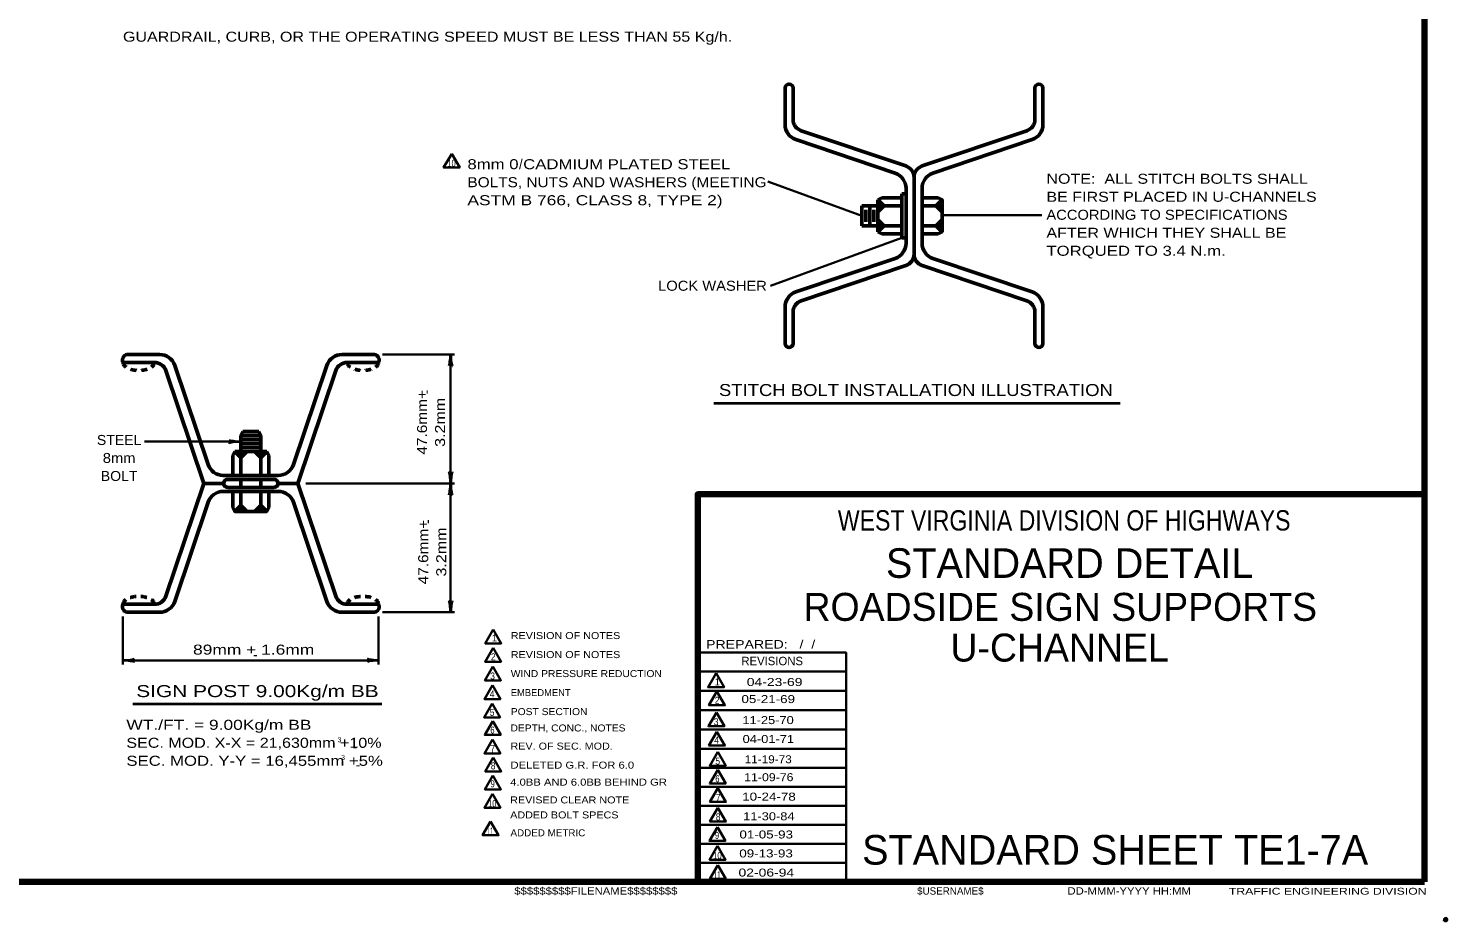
# Model space of a CAD drawing. Extents: x -39 to 816, y -2 to 542.
# Drawn here: x 390.9 to 816.3, y -1.7 to 265.9 of the extents above; entities that cross this region are included whole.
import ezdxf
from ezdxf.enums import TextEntityAlignment as Align

# ---------------------------------------------------------------- set-up
doc = ezdxf.new("R2010")
doc.units = 0
doc.header["$LTSCALE"] = 1.2
doc.header["$PDMODE"] = 32
doc.header["$PDSIZE"] = 0.6
doc.linetypes.add('SHORT_DASHED', pattern=[2.7, 1.5, -1.2])
doc.layers.add('1', color=7, linetype='Continuous', lineweight=53)
doc.layers.add('61', color=7, linetype='Continuous', lineweight=35)

msp = doc.modelspace()

# ---------------------------------------------------------------- linework, layer by layer
at = {"layer": '1', "lineweight": 158}
for q in [(809.673, 536.027), (809.673, 126.227), (18.073, 9.927)]:
    msp.add_line((809.673, 9.927), q, dxfattribs=at)
at = {"layer": '1', "lineweight": 13}
msp.add_line((809.673, 9.927), (809.673, 536.027), dxfattribs=at)
at = {"layer": '1'}
for p, q in [((617.877, 237.1), (617.877, 248.053)), ((620.277, 238.639), (620.277, 248.053)), ((692.81, 238.639), (692.81, 248.053)), ((695.21, 237.1), (695.21, 248.053)), ((654.093, 224.65), (622.727, 235.227)), ((658.993, 224.65), (690.36, 235.227)), ((650.877, 222.525), (621.143, 232.552)), ((662.209, 222.525), (691.943, 232.552)), ((656.543, 198.209), (656.543, 221.239)), ((654.143, 201.471), (654.143, 217.977)), ((658.943, 201.471), (658.943, 217.977)), ((640.943, 206.724), (640.943, 212.724)), ((643.343, 206.724), (643.343, 212.724)), ((645.743, 214.524), (646.943, 215.124)), ((645.743, 204.924), (645.743, 214.524)), ((646.943, 215.124), (652.943, 215.124)), ((654.143, 216.324), (652.943, 216.324)), ((652.943, 216.324), (652.943, 203.124)), ((658.943, 215.124), (663.743, 215.124)), ((658.943, 212.724), (664.943, 212.724)), ((664.943, 214.524), (663.743, 215.124)), ((664.943, 204.924), (664.943, 214.524)), ((642.143, 207.924), (642.143, 211.524)), ((644.543, 207.924), (644.543, 211.524)), ((645.743, 204.924), (646.943, 204.324)), ((646.943, 204.324), (652.943, 204.324)), ((658.943, 206.724), (664.943, 206.724)), ((658.943, 204.324), (663.743, 204.324)), ((664.943, 204.924), (663.743, 204.324)), ((654.143, 203.124), (652.943, 203.124)), ((650.877, 196.923), (621.143, 186.896)), ((662.209, 196.923), (691.943, 186.896)), ((654.094, 194.798), (622.727, 184.221)), ((658.993, 194.798), (690.36, 184.221)), ((617.877, 182.348), (617.877, 171.395)), ((620.277, 180.81), (620.277, 171.395)), ((692.81, 180.81), (692.81, 171.395)), ((695.21, 182.348), (695.21, 171.395)), ((430.279, 168.123), (420.526, 168.123)), ((485.031, 168.123), (494.784, 168.123)), ((428.741, 165.723), (419.326, 165.723)), ((443.555, 129.456), (432.152, 163.273)), ((444.854, 135.123), (434.827, 164.856)), ((470.457, 135.123), (480.483, 164.856)), ((471.755, 129.456), (483.158, 163.273)), ((486.57, 165.723), (495.984, 165.723)), ((455.255, 145.056), (454.655, 143.856)), ((455.255, 145.056), (460.055, 145.056)), ((460.055, 145.056), (460.655, 143.856)), ((454.655, 143.856), (460.655, 143.856)), ((454.655, 142.656), (460.655, 142.656)), ((454.655, 141.456), (460.655, 141.456)), ((452.855, 139.056), (452.255, 137.856)), ((452.255, 137.856), (452.255, 131.856)), ((452.855, 139.056), (462.455, 139.056)), ((454.655, 140.256), (460.388, 140.256)), ((462.455, 139.056), (463.055, 137.856)), ((463.055, 137.856), (463.055, 131.856)), ((449.402, 131.856), (465.908, 131.856)), ((443.555, 129.456), (432.152, 95.64)), ((443.555, 129.456), (449.492, 129.456)), ((450.755, 130.656), (464.555, 130.656)), ((450.755, 128.256), (464.555, 128.256)), ((454.655, 130.656), (454.655, 128.256)), ((460.655, 130.656), (460.655, 128.256)), ((465.818, 129.456), (471.755, 129.456)), ((471.755, 129.456), (483.158, 95.64)), ((444.854, 123.79), (434.827, 94.056)), ((449.402, 127.056), (465.908, 127.056)), ((452.255, 127.056), (452.255, 122.256)), ((454.655, 127.056), (454.655, 121.056)), ((460.655, 127.056), (460.655, 121.056)), ((463.055, 127.056), (463.055, 122.256)), ((470.457, 123.79), (480.483, 94.056)), ((452.855, 121.056), (452.255, 122.256)), ((452.855, 121.056), (462.455, 121.056)), ((462.455, 121.056), (463.055, 122.256)), ((428.741, 93.19), (419.326, 93.19)), ((430.279, 90.79), (420.526, 90.79)), ((485.031, 90.79), (494.784, 90.79)), ((486.57, 93.19), (495.984, 93.19))]:
    msp.add_line(p, q, dxfattribs=at)
at = {"layer": '1', "lineweight": 35}
for p, q in [((640.943, 209.724), (612.752, 219.985)), ((664.9, 209.888), (694.9, 209.888)), ((652.943, 203.124), (613.476, 188.759)), ((497.184, 168.123), (518.784, 168.123)), ((454.573, 141.978), (425.773, 141.978)), ((474.155, 129.456), (518.784, 129.456)), ((419.326, 89.59), (419.326, 75.19)), ((495.984, 89.59), (495.984, 75.19)), ((497.184, 90.79), (518.784, 90.79)), ((419.326, 76.39), (495.984, 76.39)), ((636.173, 73.027), (591.673, 73.027)), ((636.173, 67.227), (591.673, 67.227)), ((636.173, 61.427), (591.673, 61.427)), ((636.173, 55.627), (591.673, 55.627)), ((636.173, 49.827), (591.673, 49.827)), ((636.173, 44.127), (591.673, 44.127)), ((636.173, 38.427), (591.673, 38.427)), ((636.173, 32.727), (591.673, 32.727)), ((636.173, 27.027), (591.673, 27.027)), ((636.173, 21.327), (591.673, 21.327)), ((636.173, 15.627), (591.673, 15.627))]:
    msp.add_line(p, q, dxfattribs=at)
at = {"layer": '1', "lineweight": 40}
for p, q in [((596.486, 153.57), (718.406, 153.57)), ((422.301, 63.357), (496.961, 63.357))]:
    msp.add_line(p, q, dxfattribs=at)
at = {"layer": '1', "lineweight": 35}
for points in [[(517.894, 228.314), (515.494, 224.157), (520.294, 224.157)], [(530.384, 85.638), (527.984, 81.481), (532.784, 81.481)], [(530.312, 80.146), (527.912, 75.99), (532.712, 75.99)], [(530.24, 74.52), (527.84, 70.363), (532.64, 70.363)], [(597.203, 72.496), (594.803, 68.339), (599.603, 68.339)], [(530.136, 68.925), (527.736, 64.768), (532.536, 64.768)], [(597.446, 67.084), (595.046, 62.927), (599.846, 62.927)], [(530.033, 63.434), (527.633, 59.277), (532.433, 59.277)], [(597.295, 60.786), (594.895, 56.629), (599.695, 56.629)], [(530.209, 58.175), (527.809, 54.018), (532.609, 54.018)], [(530.136, 52.621), (527.736, 48.464), (532.536, 48.464)], [(597.446, 54.974), (595.046, 50.817), (599.846, 50.817)], [(530.369, 47.218), (527.969, 43.061), (532.769, 43.061)], [(597.675, 48.931), (595.275, 44.774), (600.075, 44.774)], [(597.675, 43.585), (595.275, 39.428), (600.075, 39.428)], [(530.281, 41.852), (527.881, 37.695), (532.681, 37.695)], [(530.106, 36.349), (527.706, 32.192), (532.506, 32.192)], [(597.76, 38.068), (595.361, 33.911), (600.161, 33.911)], [(597.748, 32.183), (595.348, 28.026), (600.148, 28.026)], [(529.574, 28.074), (527.173, 23.917), (531.974, 23.917)], [(597.574, 26.388), (595.174, 22.231), (599.974, 22.231)], [(597.635, 20.755), (595.235, 16.598), (600.035, 16.598)], [(597.714, 15.009), (595.313, 10.853), (600.114, 10.853)]]:
    msp.add_lwpolyline(points, close=True, dxfattribs=at)
at = {"layer": '1'}
for points in [[(640.943, 212.724), (645.743, 212.724), (652.943, 212.724)], [(640.943, 206.724), (645.743, 206.724), (652.943, 206.724)], [(454.655, 143.856), (454.655, 139.056), (454.655, 131.856)], [(460.655, 143.856), (460.655, 139.056), (460.655, 131.856)]]:
    msp.add_lwpolyline(points, dxfattribs=at)
for points in [[(645.743, 214.524), (645.743, 210.924), (647.543, 212.724)], [(664.943, 210.924), (663.143, 212.724), (664.943, 214.524)], [(645.743, 204.924), (645.743, 208.524), (647.543, 206.724)], [(663.143, 206.724), (664.943, 204.924), (664.943, 208.524)], [(452.855, 139.056), (456.455, 139.056), (454.655, 137.256)], [(462.455, 139.056), (458.855, 139.056), (460.655, 137.256)], [(454.655, 122.856), (452.855, 121.056), (456.455, 121.056)], [(458.855, 121.056), (460.655, 122.856), (462.455, 121.056)]]:
    msp.add_lwpolyline(points, close=True, dxfattribs=at)
at = {"layer": '1', "lineweight": 35}
for points in [[(517.584, 168.123), (517.584, 129.456), (517.584, 90.79)], [(636.173, 9.927), (636.173, 78.727), (591.673, 78.727)]]:
    msp.add_lwpolyline(points, dxfattribs=at)
at = {"layer": '1', "lineweight": 158}
msp.add_lwpolyline([(591.673, 9.927), (591.673, 126.227), (809.673, 126.227)], dxfattribs=at)
at = {"layer": '1'}
for centre, radius, start, end in [((619.077, 247.997), 1.201, 2.66716, 177.33283), ((694.009, 247.997), 1.201, 2.66716, 177.33283), ((623.877, 238.639), 3.6, 180, 251.36548), ((689.21, 238.639), 3.6, 288.63452, 0), ((622.677, 237.1), 4.8, 180, 251.36561), ((690.41, 237.1), 4.8, 288.63439, 360), ((649.343, 217.977), 4.8, 0, 71.36535), ((652.943, 221.239), 3.6, 0, 71.36649), ((660.143, 221.239), 3.6, 108.63574, 180), ((663.743, 217.977), 4.8, 108.63465, 180), ((649.343, 201.471), 4.8, 288.63525, 0), ((663.743, 201.471), 4.8, 180, 251.36475), ((652.943, 198.209), 3.6, 288.63393, 0), ((660.143, 198.209), 3.6, 180, 251.36641), ((622.677, 182.348), 4.8, 108.63408, 180), ((623.877, 180.81), 3.6, 108.63464, 180), ((689.21, 180.81), 3.6, 0, 71.36536), ((690.41, 182.348), 4.8, 0, 71.36592), ((619.077, 171.451), 1.201, 182.66717, 357.33284), ((694.009, 171.451), 1.201, 182.66717, 357.33284), ((420.844, 166.464), 1.689, 100.85533, 206.01456), ((430.279, 163.323), 4.8, 18.63408, 90), ((485.031, 163.323), 4.8, 90, 161.36561), ((494.466, 166.464), 1.689, 333.98544, 79.14467), ((428.741, 162.123), 3.6, 18.63464, 90), ((486.57, 162.123), 3.6, 90, 161.36548), ((449.402, 136.656), 4.8, 198.63525, 270), ((465.908, 136.656), 4.8, 270, 341.36535), ((450.693, 129.456), 1.202, 87.05408, 272.94592), ((464.617, 129.456), 1.202, 267.05408, 92.94592), ((449.402, 122.256), 4.8, 90, 161.36475), ((465.908, 122.256), 4.8, 18.63465, 90), ((428.741, 96.79), 3.6, 270, 341.36536), ((430.279, 95.59), 4.8, 270, 341.36592), ((485.031, 95.59), 4.8, 198.63439, 270), ((486.57, 96.79), 3.6, 198.63452, 270), ((420.844, 92.449), 1.689, 153.98544, 259.14467), ((494.466, 92.449), 1.689, 280.85533, 26.01456)]:
    msp.add_arc(centre, radius, start, end, dxfattribs=at)
at = {"layer": '1', "lineweight": 40}
for centre, major_axis, ratio, start_param, end_param in [((517.33, 166.778), (0.211, 2.108), 0.07063, 3.1407148, 5.41811), ((517.33, 166.778), (0.211, 2.108), 0.07063, 3.1407148, 5.41811), ((517.916, 166.813), (-0.187, 2.143), 0.122415, 0.8963533, 3.1415927), ((517.916, 166.813), (-0.187, 2.143), 0.122415, 0.8963533, 3.1415927), ((453.263, 141.647), (2.143, 0.187), 0.122415, 0.8963533, 3.1415927), ((453.228, 142.232), (2.108, -0.211), 0.07063, 3.1407148, 5.41811), ((517.253, 130.766), (0.187, -2.143), 0.122415, 0.8963533, 3.1415927), ((517.253, 130.766), (0.187, -2.143), 0.122415, 0.8963533, 3.1415927), ((517.838, 130.801), (-0.211, -2.108), 0.07063, 3.1407148, 5.41811), ((517.838, 130.801), (-0.211, -2.108), 0.07063, 3.1407148, 5.41811), ((517.33, 128.112), (0.211, 2.108), 0.07063, 3.1407148, 5.41811), ((517.33, 128.112), (0.211, 2.108), 0.07063, 3.1407148, 5.41811), ((517.916, 128.147), (-0.187, 2.143), 0.122415, 0.8963533, 3.1415927), ((517.916, 128.147), (-0.187, 2.143), 0.122415, 0.8963533, 3.1415927), ((517.253, 92.1), (0.187, -2.143), 0.122415, 0.8963533, 3.1415927), ((517.838, 92.135), (-0.211, -2.108), 0.07063, 3.1407148, 5.41811), ((420.635, 76.722), (-2.143, -0.187), 0.122415, 0.8963533, 3.1415927), ((420.635, 76.722), (-2.143, -0.187), 0.122415, 0.8963533, 3.1415927), ((494.64, 76.644), (2.108, -0.211), 0.07063, 3.1407148, 5.41811), ((420.67, 76.136), (-2.108, 0.211), 0.07063, 3.1407148, 5.41811), ((420.67, 76.136), (-2.108, 0.211), 0.07063, 3.1407148, 5.41811), ((494.675, 76.059), (2.143, 0.187), 0.122415, 0.8963533, 3.1415927)]:
    msp.add_ellipse(centre, major_axis=major_axis, ratio=ratio, start_param=start_param, end_param=end_param, dxfattribs=at)
at = {"layer": '1', "linetype": 'SHORT_DASHED'}
for centre, major_axis, start_param, end_param in [((424.033, 165.723), (4.707, 0), 3.1415927, 6.2831853), ((491.277, 165.723), (-4.707, 0), 6.2831853, 9.424778), ((424.033, 93.19), (4.707, 0), 6.2831853, 9.424778), ((491.277, 93.19), (-4.707, 0), 3.1415927, 6.2831853)]:
    msp.add_ellipse(centre, major_axis=major_axis, ratio=0.50983, start_param=start_param, end_param=end_param, dxfattribs=at)
at = {"layer": '1'}
msp.add_point((815.973, -1.373), dxfattribs=at)
at = {"layer": '61', "lineweight": 53}
for q in [(656.973, 9.927), (656.973, 9.927), (656.973, 9.927), (657.273, 9.927), (657.273, 9.927)]:
    msp.add_line((809.673, 9.927), q, dxfattribs=at)

# ---------------------------------------------------------------- texts
at = {"layer": '1'}
for s, height, width, p in [('GUARDRAIL, CURB, OR THE OPERATING SPEED MUST BE LESS THAN 55 Kg/h.', 3, 1.2, (419.317, 261.927)), ('10', 2.1, 0.8, (516.601, 224.428)), ('8mm 0 CADMIUM PLATED STEEL', 3, 1.25, (522.621, 223.689)), ('BOLTS, NUTS AND WASHERS (MEETING', 3, 1.15, (522.621, 218.289)), ('NOTE:  ALL STITCH BOLTS SHALL', 3, 1.2, (696.249, 219.32)), ('BE FIRST PLACED IN U-CHANNELS', 3, 1.2, (696.249, 213.92)), ('ASTM B 766, CLASS 8, TYPE 2)', 3, 1.3, (522.621, 212.889)), ('ACCORDING TO SPECIFICATIONS', 3, 1.1, (696.249, 208.52)), ('AFTER WHICH THEY SHALL BE', 3, 1.2, (696.249, 203.12)), ('TORQUED TO 3.4 N.m.', 3, 1.25, (696.249, 197.72)), ('REVISION OF NOTES', 2.1, 1.15, (535.623, 82.767)), ('PREPARED:   /  /  ', 2.537, 1.25, (594.173, 79.927)), ('2', 2.1, 0.9, (529.675, 76.416)), ('REVISION OF NOTES', 2.1, 1.15, (535.623, 77.067)), ('3', 2.1, 0.9, (529.458, 70.645)), ('WIND PRESSURE REDUCTION', 2.1, 1.1, (535.623, 71.367)), ('4', 2.1, 0.95, (529.283, 65.252)), ('2', 2.1, 0.9, (596.809, 63.354)), ('5', 2.1, 0.9, (529.323, 59.72)), ('POST SECTION', 2.1, 1.1, (535.623, 59.967)), ('WT./FT. = 9.00Kg/m BB', 3, 1.3, (420.343, 55.562)), ('6', 2.1, 0.8, (529.499, 54.445)), ('DEPTH, CONC., NOTES', 2.1, 1.1, (535.535, 55.059)), ('3', 2.1, 0.9, (596.513, 56.911)), ('SEC. MOD. X-X = 21,630mm +10%', 3, 1.2, (420.343, 50.162)), ('3', 1.5, 0.9, (483.686, 51.823)), ('REV. OF SEC. MOD.', 2.1, 1.15, (535.535, 49.622)), ('4', 2.1, 0.95, (596.592, 51.388)), ('SEC. MOD. Y-Y = 16,455mm +5%', 3, 1.25, (420.343, 44.762)), ('3', 1.5, 0.9, (484.751, 46.539)), ('7', 2.1, 0.9, (529.499, 48.835)), ('5', 2.1, 0.9, (596.966, 45.129)), ('8', 2.1, 0.9, (529.644, 43.679)), ('DELETED G.R. FOR 6.0', 2.1, 1.2, (535.535, 43.922)), ('9', 2.1, 0.8, (529.556, 38.313)), ('4.0BB AND 6.0BB BEHIND GR', 2.1, 1.2, (535.447, 38.82)), ('6', 2.1, 0.8, (596.966, 39.855)), ('10', 2.1, 0.8, (528.813, 32.374)), ('REVISED CLEAR NOTE', 2.1, 1.15, (535.447, 33.479)), ('7', 2.1, 0.9, (597.123, 34.193)), ('ADDED BOLT SPECS', 2.1, 1.15, (535.447, 28.979)), ('8', 2.1, 0.9, (597.111, 28.381)), ('11', 2.1, 0.55, (528.281, 24.099)), ('ADDED METRIC', 2.1, 1.05, (535.535, 23.617)), ('9', 2.1, 0.8, (596.849, 22.85)), ('10', 2.1, 0.8, (596.343, 16.78)), ('11', 2.1, 0.55, (596.421, 11.035)), ('$$$$$$$$$FILENAME$$$$$$$$', 2.2, 1.15, (536.673, 6.127)), ('DD-MMM-YYYY HH:MM', 2.2, 1.15, (702.573, 6.127)), ('TRAFFIC ENGINEERING DIVISION', 2.031, 1.35, (750.973, 6.127))]:
    msp.add_text(s, height=height, dxfattribs=dict(at, width=width)).set_placement(p)
for s, height, p in [('/', 3, (538.631, 223.66)), ('STANDARD DETAIL', 8.881, (703.223, 101.127)), ('ROADSIDE SIGN SUPPORTS', 8.391, (700.407, 88.235)), ('U-CHANNEL', 8.391, (700.207, 76.024)), ('-', 3, (459.054, 76.648)), ('-', 3, (488.879, 48.971)), ('-', 3, (489.808, 43.608))]:
    msp.add_text(s, height=height, dxfattribs=at).set_placement(p, align=Align.CENTER)
for s, height, width, p in [('LOCK WASHER', 3, 1.1, (596.109, 187.233)), ('STITCH BOLT INSTALLATION ILLUSTRATION', 3.6, 1.15, (657.122, 155.663)), ('STEEL', 3, 1.05, (418.17, 140.985)), ('8mm', 3, 1.1, (418.17, 135.585)), ('BOLT', 3, 1.05, (418.17, 130.185)), ('WEST VIRGINIA DIVISION OF HIGHWAYS', 6.089, 0.85, (701.573, 115.327)), ('89mm + 1.6mm', 3, 1.3, (458.515, 78.108)), ('SIGN POST 9.00Kg/m BB', 3.6, 1.3, (459.652, 65.368)), ('04-23-69', 2.4, 1.3, (614.742, 68.695)), ('05-21-69', 2.4, 1.25, (612.83, 63.572)), ('11-25-70', 2.4, 1.2, (612.775, 57.269)), ('04-01-71', 2.4, 1.2, (612.854, 51.595)), ('11-19-73', 2.4, 1.1, (612.819, 45.525)), ('11-09-76', 2.4, 1.15, (613.011, 40.148)), ('10-24-78', 2.4, 1.25, (613.049, 34.314)), ('11-30-84', 2.4, 1.2, (613.011, 28.424)), ('01-05-93', 2.4, 1.25, (612.221, 22.971)), ('09-13-93', 2.4, 1.25, (612.178, 17.286)), ('02-06-94', 2.4, 1.3, (612.265, 11.541))]:
    msp.add_text(s, height=height, dxfattribs=dict(at, width=width)).set_placement(p, align=Align.CENTER)
for s, width, p in [('47.6mm+', 1.15, (510.505, 147.769)), ('3.2mm', 1.2, (515.905, 147.769)), ('47.6mm+', 1.15, (510.86, 108.875)), ('3.2mm', 1.2, (516.26, 108.875))]:
    msp.add_text(s, height=3, rotation=90, dxfattribs=dict(at, width=width)).set_placement(p, align=Align.CENTER)
for p in [(511.699, 156.878), (512.054, 117.983)]:
    msp.add_text('-', height=3, rotation=90, dxfattribs=at).set_placement(p, align=Align.CENTER)
for s, height, p in [('1', 2.1, (529.964, 82.052)), ('REVISIONS', 2.537, (604.773, 74.927)), ('1', 2.1, (596.783, 68.911)), ('EMBEDMENT', 2.1, (535.623, 65.667)), ('STANDARD SHEET TE1-7A', 8.881, (640.973, 15.127)), ('$USERNAME$', 2.2, (657.473, 6.127))]:
    msp.add_text(s, height=height, dxfattribs=at).set_placement(p)

doc.saveas('drawing.dxf')
